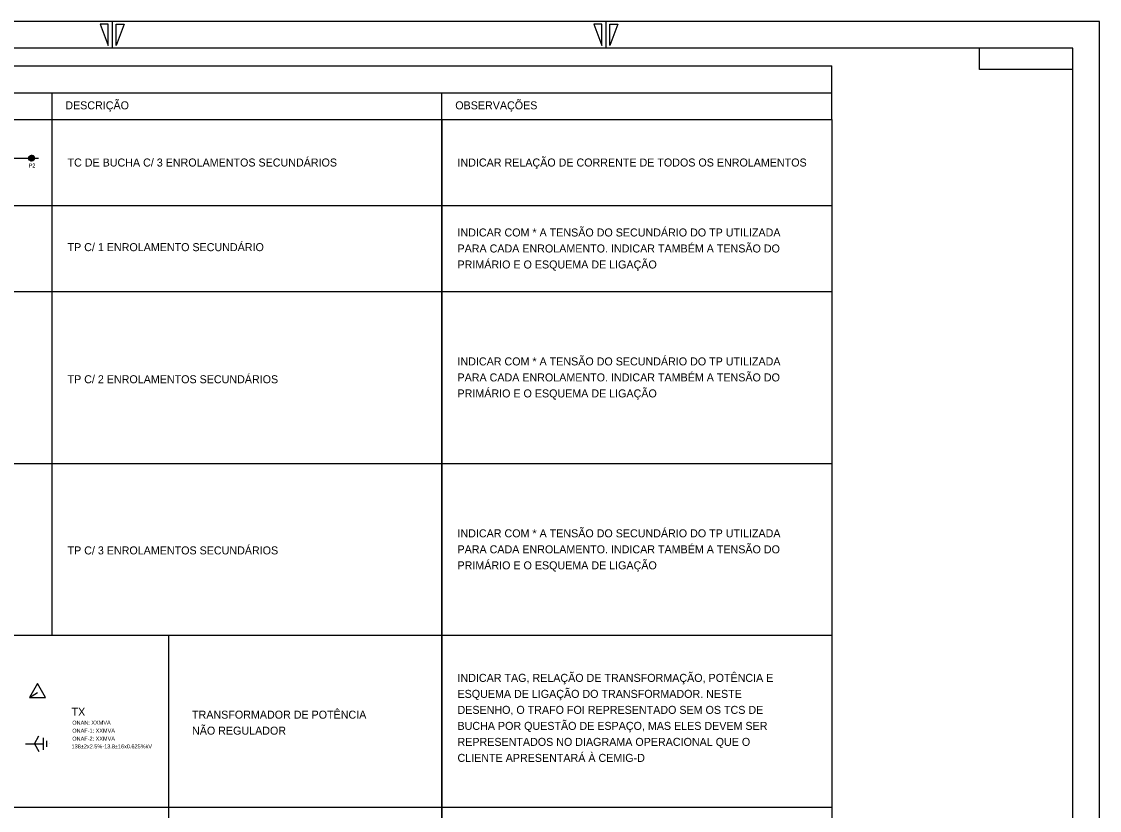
# Model space of a CAD drawing. Extents: x 563 to 3226, y 358 to 960.
# Drawn here: x 999.7 to 1403.6, y 656.2 to 952 of the extents above; entities that cross this region are included whole.
import ezdxf

# ---------------------------------------------------------------- set-up
doc = ezdxf.new("R2010")
doc.units = 0
doc.layers.add('Default', color=7, linetype='Continuous')
doc.layers.add('New Level (0)', color=7, linetype='Continuous')

msp = doc.modelspace()

# ---------------------------------------------------------------- linework, layer by layer
at = {"layer": 'Default'}
for p, q in [((957.79, 900.78), (1006.04, 900.78)), ((1002.33, 900.83), (1003.51, 899.65)), ((1002.35, 901), (1003.68, 899.68)), ((1002.4, 901.15), (1003.83, 899.73)), ((1002.46, 901.29), (1003.96, 899.79)), ((1002.54, 901.41), (1004.08, 899.86)), ((1002.62, 901.51), (1004.19, 899.95)), ((1002.73, 901.61), (1004.28, 900.05)), ((1002.84, 901.69), (1004.36, 900.17)), ((1002.97, 901.76), (1004.43, 900.29)), ((1003.11, 901.81), (1004.49, 900.43)), ((1003.27, 901.85), (1004.52, 900.59)), ((1003.45, 901.86), (1004.54, 900.78)), ((1003.67, 901.84), (1004.51, 901)), ((1003.99, 901.71), (1004.38, 901.32)), ((1002.33, 900.63), (1003.31, 899.66)), ((1002.39, 900.38), (1003.05, 899.72)), ((1005.63, 703.81), (1002.6, 698.58)), ((1008.65, 698.58), (1005.63, 703.81)), ((1002.6, 698.58), (1005.69, 700.45)), ((1002.6, 698.58), (1008.65, 698.58)), ((1004.5, 681.16), (1006.19, 684.1)), ((1007.89, 678.9), (1007.89, 683.42)), ((1001.1, 681.16), (1007.89, 681.16)), ((1004.5, 681.16), (1006.19, 678.22)), ((1009.02, 682.29), (1009.02, 680.03)), ((1010.15, 681.16), (1010.15, 681.16))]:
    msp.add_line(p, q, dxfattribs=at)
msp.add_circle((1003.43, 900.76), 1.11, dxfattribs=at)
at = {"layer": 'New Level (0)'}
for p, q in [((1403.58, 951.96), (562.58, 951.96)), ((1403.58, 951.96), (562.58, 951.96)), ((1032.08, 950.96), (1029.08, 950.96)), ((1029.08, 950.96), (1032.08, 942.96)), ((1032.08, 942.96), (1032.08, 950.96)), ((1033.58, 951.96), (1033.58, 941.96)), ((1035.08, 942.96), (1035.08, 950.96)), ((1035.08, 950.96), (1038.08, 950.96)), ((1038.08, 950.96), (1035.08, 942.96)), ((1217.08, 950.96), (1214.08, 950.96)), ((1214.08, 950.96), (1217.08, 942.96)), ((1217.08, 942.96), (1217.08, 950.96)), ((1218.58, 951.96), (1218.58, 941.96)), ((1220.08, 942.96), (1220.08, 950.96)), ((1220.08, 950.96), (1223.08, 950.96)), ((1223.08, 950.96), (1220.08, 942.96)), ((1403.58, 357.96), (1403.58, 951.96)), ((1403.58, 357.96), (1403.58, 951.96)), ((1393.58, 941.96), (572.58, 941.96)), ((1358.58, 933.96), (1358.58, 941.96)), ((1393.58, 367.96), (1393.58, 941.96)), ((1393.58, 367.96), (1393.58, 941.96)), ((603.14, 935.35), (1303.31, 935.35)), ((1303.31, 915.21), (1303.31, 935.35)), ((1393.58, 933.96), (1358.58, 933.96)), ((953.22, 925.28), (1303.31, 925.28)), ((1011.06, 925.28), (1011.06, 721.84)), ((1157.18, 915.21), (1157.18, 925.28)), ((603.14, 882.98), (1303.31, 882.98)), ((603.14, 850.75), (1303.31, 850.75)), ((603.14, 786.3), (1303.31, 786.3)), ((603.14, 721.84), (1303.31, 721.84)), ((1054.73, 721.84), (1054.73, 429.83)), ((603.14, 657.39), (1303.31, 657.39))]:
    msp.add_line(p, q, dxfattribs=at)
for points in [[(953.22, 915.21), (1157.18, 915.21), (1157.18, 429.83), (953.22, 429.83)], [(1157.18, 915.21), (1303.31, 915.21), (1303.31, 429.83), (1157.18, 429.83)]]:
    msp.add_lwpolyline(points, close=True, dxfattribs=at)

# ---------------------------------------------------------------- texts
at = {"layer": 'Default'}
for s, height, p in [('DESCRIÇÃO', 3, (1016.07, 919.04)), ('OBSERVAÇÕES', 3, (1162.2, 919.04)), ('TC DE BUCHA C/ 3 ENROLAMENTOS SECUNDÁRIOS', 3, (1016.91, 897.6)), ('INDICAR RELAÇÃO DE CORRENTE DE TODOS OS ENROLAMENTOS', 3, (1163.03, 897.6)), ('P2', 1.5, (1002.32, 897.23)), ('INDICAR COM * A TENSÃO DO SECUNDÁRIO DO TP UTILIZADA ', 3, (1163.03, 871.37)), ('TP C/ 1 ENROLAMENTO SECUNDÁRIO', 3, (1016.91, 865.87)), ('PARA CADA ENROLAMENTO. INDICAR TAMBÉM A TENSÃO DO ', 3, (1163.03, 865.37)), ('PRIMÁRIO E O ESQUEMA DE LIGAÇÃO', 3, (1163.03, 859.37)), ('INDICAR COM * A TENSÃO DO SECUNDÁRIO DO TP UTILIZADA ', 3, (1163.03, 823.03)), ('TP C/ 2 ENROLAMENTOS SECUNDÁRIOS', 3, (1016.91, 816.34)), ('PARA CADA ENROLAMENTO. INDICAR TAMBÉM A TENSÃO DO ', 3, (1163.03, 817.03)), ('PRIMÁRIO E O ESQUEMA DE LIGAÇÃO', 3, (1163.03, 811.03)), ('INDICAR COM * A TENSÃO DO SECUNDÁRIO DO TP UTILIZADA ', 3, (1163.03, 758.57)), ('TP C/ 3 ENROLAMENTOS SECUNDÁRIOS', 3, (1016.91, 752.17)), ('PARA CADA ENROLAMENTO. INDICAR TAMBÉM A TENSÃO DO ', 3, (1163.03, 752.57)), ('PRIMÁRIO E O ESQUEMA DE LIGAÇÃO', 3, (1163.03, 746.57)), ('INDICAR TAG, RELAÇÃO DE TRANSFORMAÇÃO, POTÊNCIA E ', 3, (1163.03, 704.38)), ('ESQUEMA DE LIGAÇÃO DO TRANSFORMADOR. NESTE ', 3, (1163.03, 698.38)), ('DESENHO, O TRAFO FOI REPRESENTADO SEM OS TCS DE ', 3, (1163.03, 692.38)), ('TX', 3, (1018.41, 691.67)), ('TRANSFORMADOR DE POTÊNCIA', 3, (1063.56, 690.59)), ('ONAN: XXMVA', 1.5, (1018.69, 688.34)), ('ONAF-1: XXMVA', 1.5, (1018.69, 685.34)), ('NÃO REGULADOR', 3, (1063.56, 684.59)), ('BUCHA POR QUESTÃO DE ESPAÇO, MAS ELES DEVEM SER ', 3, (1163.03, 686.38)), ('ONAF-2: XXMVA', 1.5, (1018.69, 682.34)), ('REPRESENTADOS NO DIAGRAMA OPERACIONAL QUE O ', 3, (1163.03, 680.38)), ('138±2x2.5%-13.8±16x0.625%kV', 1.5, (1018.43, 679.44)), ('CLIENTE APRESENTARÁ À CEMIG-D', 3, (1163.03, 674.38))]:
    msp.add_text(s, height=height, dxfattribs=at).set_placement(p)

doc.saveas('drawing.dxf')
